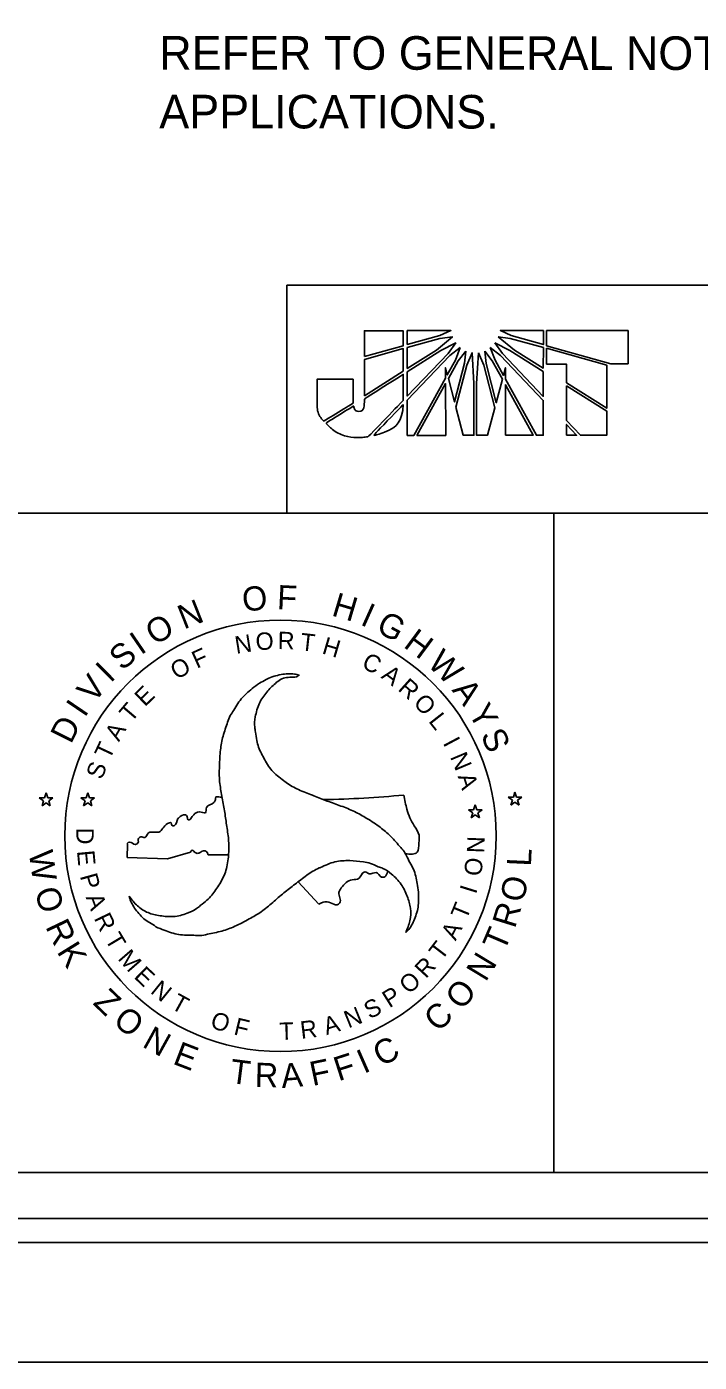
# Model space of a CAD drawing. Extents: x 1403867 to 1405555, y 486423 to 487523.
# Drawn here: x 1405174.3 to 1405314.5, y 486422.7 to 486701.2 of the extents above; entities that cross this region are included whole.
import ezdxf

# ---------------------------------------------------------------- set-up
doc = ezdxf.new("R2010")
doc.units = 0
for name, color, linetype in [('Default', 7, 'Continuous'), ('DEV BORDER CELL', 7, 'Continuous'), ('DEV DOT SWIRL SEAL CELL', 7, 'Continuous'), ('Sheet Plan CELL', 7, 'Continuous'), ('Sheet Plot Border Outside CELL', 7, 'Continuous'), ('Text', 7, 'Continuous')]:
    doc.layers.add(name, color=color, linetype=linetype)

msp = doc.modelspace()

# ---------------------------------------------------------------- linework, layer by layer
at = {"layer": 'Default'}
for p, q in [((1405252.78, 486637.79), (1405244.69, 486637.79)), ((1405244.69, 486637.79), (1405244.69, 486632.42)), ((1405252.79, 486634.67), (1405252.78, 486637.79)), ((1405262.74, 486637.84), (1405253.62, 486637.83)), ((1405253.62, 486637.83), (1405253.63, 486634.94)), ((1405253.63, 486634.94), (1405260.41, 486636.81)), ((1405260.41, 486636.18), (1405253.63, 486634.31)), ((1405259.71, 486633.78), (1405263.06, 486636.51)), ((1405260.41, 486636.81), (1405262.74, 486637.84)), ((1405263.06, 486636.51), (1405260.41, 486636.18)), ((1405272.6, 486636.52), (1405275.99, 486633.74)), ((1405275.1, 486636.2), (1405272.6, 486636.52)), ((1405282.03, 486637.82), (1405273.05, 486637.85)), ((1405273.05, 486637.85), (1405275.32, 486636.79)), ((1405282.03, 486634.29), (1405275.1, 486636.2)), ((1405275.32, 486636.79), (1405282.03, 486634.91)), ((1405282.03, 486634.91), (1405282.03, 486637.82)), ((1405299.68, 486637.88), (1405282.66, 486637.86)), ((1405282.66, 486637.86), (1405282.66, 486634.73)), ((1405299.68, 486630.9), (1405299.68, 486637.88)), ((1405244.69, 486632.42), (1405252.79, 486634.67)), ((1405252.79, 486634.08), (1405244.69, 486631.8)), ((1405252.79, 486629.39), (1405252.79, 486634.08)), ((1405253.63, 486634.31), (1405253.63, 486629.93)), ((1405253.63, 486629.93), (1405259.71, 486633.78)), ((1405260.64, 486633.69), (1405253.63, 486629.22)), ((1405253.64, 486624.17), (1405262.17, 486633.06)), ((1405262.51, 486632.62), (1405253.64, 486623.31)), ((1405263.73, 486635.25), (1405260.64, 486633.69)), ((1405262.17, 486633.06), (1405263.73, 486635.25)), ((1405264.66, 486634.28), (1405262.51, 486632.62)), ((1405263.68, 486631.69), (1405264.66, 486634.28)), ((1405265.83, 486633.56), (1405264.22, 486631.5)), ((1405265.6, 486631.06), (1405265.83, 486633.56)), ((1405267.16, 486633.2), (1405266.06, 486630.61)), ((1405267.52, 486626.81), (1405267.16, 486633.2)), ((1405268.5, 486633.2), (1405268.09, 486626.81)), ((1405269.57, 486630.61), (1405268.5, 486633.2)), ((1405269.79, 486633.56), (1405270.06, 486630.97)), ((1405271.36, 486631.5), (1405269.79, 486633.56)), ((1405270.94, 486634.28), (1405271.93, 486631.69)), ((1405273.09, 486632.63), (1405270.94, 486634.28)), ((1405271.89, 486635.26), (1405273.46, 486633.03)), ((1405275.02, 486633.7), (1405271.89, 486635.26)), ((1405281.99, 486623.26), (1405273.09, 486632.63)), ((1405273.46, 486633.03), (1405281.99, 486624.1)), ((1405281.98, 486629.28), (1405275.02, 486633.7)), ((1405275.99, 486633.74), (1405281.98, 486630)), ((1405281.98, 486630), (1405282.03, 486634.29)), ((1405282.66, 486634.73), (1405282.66, 486634.64)), ((1405282.66, 486634.64), (1405296.06, 486630.9)), ((1405282.66, 486634.16), (1405282.66, 486634.11)), ((1405295.21, 486630.59), (1405282.66, 486634.16)), ((1405282.66, 486634.11), (1405282.66, 486630.85)), ((1405244.69, 486631.8), (1405244.7, 486624.25)), ((1405261.58, 486627.93), (1405261.58, 486630.07)), ((1405261.58, 486630.07), (1405261.98, 486628.6)), ((1405261.98, 486628.6), (1405263.68, 486631.69)), ((1405264.22, 486631.5), (1405262.21, 486627.84)), ((1405263.51, 486622.97), (1405265.6, 486631.06)), ((1405266.06, 486630.61), (1405263.78, 486621.85)), ((1405271.9, 486621.73), (1405269.57, 486630.61)), ((1405270.06, 486630.97), (1405272.17, 486622.79)), ((1405273.46, 486627.71), (1405271.36, 486631.5)), ((1405271.93, 486631.69), (1405273.67, 486628.47)), ((1405273.67, 486628.47), (1405274.09, 486630.08)), ((1405274.09, 486630.08), (1405274.09, 486627.71)), ((1405282.66, 486630.85), (1405286.82, 486630.85)), ((1405286.82, 486630.85), (1405286.82, 486626.96)), ((1405295.22, 486621.65), (1405295.21, 486630.59)), ((1405296.06, 486630.9), (1405299.68, 486630.9)), ((1405244.7, 486624.25), (1405252.79, 486629.39)), ((1405253.63, 486629.22), (1405253.64, 486624.17)), ((1405254.98, 486615.97), (1405261.58, 486627.93)), ((1405262.21, 486627.84), (1405263.51, 486622.97)), ((1405272.17, 486622.79), (1405273.46, 486627.71)), ((1405274.09, 486627.71), (1405280.56, 486615.99)), ((1405281.99, 486624.1), (1405281.98, 486629.28)), ((1405261.58, 486626.77), (1405255.61, 486615.97)), ((1405261.65, 486615.97), (1405261.58, 486626.77)), ((1405267.52, 486616.02), (1405267.52, 486626.81)), ((1405268.09, 486626.81), (1405268.1, 486616.02)), ((1405279.9, 486616.03), (1405274.09, 486626.55)), ((1405274.09, 486626.55), (1405274.1, 486616.02)), ((1405286.82, 486626.96), (1405295.22, 486621.65)), ((1405286.82, 486626.29), (1405286.83, 486619.05)), ((1405295.22, 486621.03), (1405286.82, 486626.29)), ((1405253.64, 486623.31), (1405253.64, 486615.96)), ((1405263.78, 486621.85), (1405265.31, 486616.01)), ((1405270.34, 486616.02), (1405271.9, 486621.73)), ((1405281.99, 486615.99), (1405281.99, 486623.26)), ((1405286.83, 486619.05), (1405289.73, 486616)), ((1405295.22, 486616), (1405295.22, 486621.03)), ((1405253.64, 486615.96), (1405254.98, 486615.97)), ((1405255.61, 486615.97), (1405261.65, 486615.97)), ((1405265.31, 486616.01), (1405267.52, 486616.02)), ((1405268.1, 486616.02), (1405270.34, 486616.02)), ((1405274.1, 486616.02), (1405279.9, 486616.03)), ((1405280.56, 486615.99), (1405281.99, 486615.99)), ((1405288.93, 486616), (1405286.83, 486618.27)), ((1405286.83, 486618.27), (1405286.83, 486615.99)), ((1405286.83, 486615.99), (1405288.93, 486616)), ((1405289.73, 486616), (1405295.22, 486616))]:
    msp.add_line(p, q, dxfattribs=at)
for points in [[(1405244.69, 486632.42), (1405252.79, 486634.67), (1405252.78, 486637.79), (1405244.69, 486637.79), (1405244.69, 486632.42)], [(1405260.41, 486636.81), (1405262.74, 486637.84), (1405253.62, 486637.83), (1405253.63, 486634.94), (1405260.41, 486636.81)], [(1405253.63, 486634.31), (1405253.63, 486629.93), (1405259.71, 486633.78), (1405263.06, 486636.51), (1405260.41, 486636.18), (1405253.63, 486634.31)], [(1405272.6, 486636.52), (1405275.99, 486633.74), (1405281.98, 486630), (1405282.03, 486634.29), (1405275.1, 486636.2), (1405272.6, 486636.52)], [(1405275.32, 486636.79), (1405282.03, 486634.91), (1405282.03, 486637.82), (1405273.05, 486637.85), (1405275.32, 486636.79)], [(1405244.7, 486624.25), (1405252.79, 486629.39), (1405252.79, 486634.08), (1405244.69, 486631.8), (1405244.7, 486624.25)], [(1405253.63, 486629.22), (1405253.64, 486624.17), (1405262.17, 486633.06), (1405263.73, 486635.25), (1405260.64, 486633.69), (1405253.63, 486629.22)], [(1405264.66, 486634.28), (1405262.51, 486632.62), (1405253.64, 486623.31), (1405253.64, 486615.96), (1405254.98, 486615.97), (1405261.58, 486627.93), (1405261.58, 486630.07), (1405261.98, 486628.6), (1405263.68, 486631.69), (1405264.66, 486634.28)], [(1405265.83, 486633.56), (1405264.22, 486631.5), (1405262.21, 486627.84), (1405263.51, 486622.97), (1405265.6, 486631.06), (1405265.83, 486633.56)], [(1405266.06, 486630.61), (1405263.78, 486621.85), (1405265.31, 486616.01), (1405267.52, 486616.02), (1405267.52, 486626.81), (1405267.16, 486633.2), (1405266.06, 486630.61)], [(1405268.5, 486633.2), (1405268.09, 486626.81), (1405268.1, 486616.02), (1405270.34, 486616.02), (1405271.9, 486621.73), (1405269.57, 486630.61), (1405268.5, 486633.2)], [(1405269.79, 486633.56), (1405270.06, 486630.97), (1405272.17, 486622.79), (1405273.46, 486627.71), (1405271.36, 486631.5), (1405269.79, 486633.56)], [(1405270.94, 486634.28), (1405271.93, 486631.69), (1405273.67, 486628.47), (1405274.09, 486630.08), (1405274.09, 486627.71), (1405280.56, 486615.99), (1405281.99, 486615.99), (1405281.99, 486623.26), (1405273.09, 486632.63), (1405270.94, 486634.28)], [(1405271.89, 486635.26), (1405273.46, 486633.03), (1405281.99, 486624.1), (1405281.98, 486629.28), (1405275.02, 486633.7), (1405271.89, 486635.26)], [(1405282.66, 486634.16), (1405282.66, 486634.11), (1405282.66, 486630.85), (1405286.82, 486630.85), (1405286.82, 486626.96), (1405295.22, 486621.65), (1405295.21, 486630.59), (1405282.66, 486634.16)], [(1405255.61, 486615.97), (1405261.65, 486615.97), (1405261.58, 486626.77), (1405255.61, 486615.97)], [(1405274.1, 486616.02), (1405279.9, 486616.03), (1405274.09, 486626.55), (1405274.1, 486616.02)], [(1405286.82, 486626.29), (1405286.83, 486619.05), (1405289.73, 486616), (1405295.22, 486616), (1405295.22, 486621.03), (1405286.82, 486626.29), (1405286.82, 486626.29)], [(1405286.83, 486615.99), (1405286.83, 486615.99), (1405288.93, 486616), (1405286.83, 486618.27), (1405286.83, 486615.99)]]:
    msp.add_lwpolyline(points, dxfattribs=at)
for points in [[(1405242.37, 486627.72), (1405242.37, 486627.72), (1405234.88, 486627.72), (1405234.88, 486627.72), (1405234.88, 486627.72), (1405234.88, 486623.03), (1405234.88, 486623.03), (1405234.88, 486623.03), (1405234.88, 486622.53), (1405234.88, 486622.53), (1405234.88, 486621.06), (1405235.36, 486619.9), (1405236.22, 486618.93), (1405236.22, 486618.93), (1405242.37, 486622.67), (1405242.37, 486622.77), (1405242.37, 486622.77), (1405242.37, 486627.72), (1405242.37, 486627.72)], [(1405242.37, 486627.72), (1405242.37, 486627.72), (1405234.88, 486627.72), (1405234.88, 486627.72), (1405234.88, 486627.72), (1405234.88, 486623.03), (1405234.88, 486623.03), (1405234.88, 486623.03), (1405234.88, 486622.53), (1405234.88, 486622.53), (1405234.88, 486621.06), (1405235.36, 486619.9), (1405236.22, 486618.93), (1405236.22, 486618.93), (1405242.37, 486622.67), (1405242.37, 486622.77), (1405242.37, 486622.77), (1405242.37, 486627.72), (1405242.37, 486627.72)], [(1405243.54, 486620.98), (1405243.06, 486620.98), (1405242.64, 486621.25), (1405242.47, 486622.14), (1405242.47, 486622.14), (1405236.66, 486618.54), (1405236.66, 486618.54), (1405238.45, 486616.66), (1405241.31, 486615.54), (1405243.73, 486615.54), (1405244.36, 486615.54), (1405244.84, 486615.6), (1405245.51, 486615.73), (1405245.51, 486615.73), (1405252.8, 486623.27), (1405252.8, 486623.27), (1405252.8, 486623.27), (1405252.79, 486628.72), (1405252.79, 486628.72), (1405252.79, 486628.72), (1405244.7, 486623.57), (1405244.7, 486623.57), (1405244.7, 486621.53), (1405244.21, 486620.98), (1405243.54, 486620.98)], [(1405243.54, 486620.98), (1405243.06, 486620.98), (1405242.64, 486621.25), (1405242.47, 486622.14), (1405242.47, 486622.14), (1405236.66, 486618.54), (1405236.66, 486618.54), (1405238.45, 486616.66), (1405241.31, 486615.54), (1405243.73, 486615.54), (1405244.36, 486615.54), (1405244.84, 486615.6), (1405245.51, 486615.73), (1405245.51, 486615.73), (1405252.8, 486623.27), (1405252.8, 486623.27), (1405252.8, 486623.27), (1405252.79, 486628.72), (1405252.79, 486628.72), (1405252.79, 486628.72), (1405244.7, 486623.57), (1405244.7, 486623.57), (1405244.7, 486621.53), (1405244.21, 486620.98), (1405243.54, 486620.98)], [(1405252.8, 486622.42), (1405252.8, 486622.42), (1405246.5, 486615.9), (1405246.5, 486615.9), (1405249.58, 486616.67), (1405252.65, 486618.72), (1405252.8, 486622.42)], [(1405252.8, 486622.42), (1405252.8, 486622.42), (1405246.5, 486615.9), (1405246.5, 486615.9), (1405249.58, 486616.67), (1405252.65, 486618.72), (1405252.8, 486622.42)]]:
    msp.add_open_spline(points, degree=3, dxfattribs=at)
at = {"layer": 'DEV BORDER CELL'}
for p, q in [((1404608.13, 486452.72), (1405520.08, 486452.72)), ((1404040.64, 486447.72), (1405520.08, 486447.72))]:
    msp.add_line(p, q, dxfattribs=at)
for points in [[(1405170.21, 486599.77), (1405284.21, 486599.77), (1405284.21, 486462.27), (1405170.21, 486462.27)], [(1405520.21, 486599.77), (1405284.21, 486599.77), (1405284.21, 486462.27), (1405520.21, 486462.27)]]:
    msp.add_lwpolyline(points, close=True, dxfattribs=at)
at = {"layer": 'DEV DOT SWIRL SEAL CELL'}
for p, q in [((1405178.35, 486541.44), (1405178.03, 486540.44)), ((1405178.71, 486540.44), (1405178.35, 486541.44)), ((1405187.02, 486541.42), (1405186.7, 486540.42)), ((1405187.39, 486540.42), (1405187.02, 486541.42)), ((1405276.07, 486541.58), (1405275.75, 486540.58)), ((1405276.43, 486540.58), (1405276.07, 486541.58)), ((1405176.94, 486540.44), (1405177.82, 486539.79)), ((1405178.03, 486540.44), (1405176.94, 486540.44)), ((1405177.82, 486539.79), (1405177.5, 486538.75)), ((1405177.5, 486538.75), (1405178.35, 486539.39)), ((1405178.35, 486539.39), (1405179.23, 486538.75)), ((1405178.35, 486539.39), (1405179.23, 486538.75)), ((1405179.79, 486540.44), (1405178.71, 486540.44)), ((1405178.91, 486539.79), (1405179.79, 486540.44)), ((1405178.91, 486539.79), (1405179.79, 486540.44)), ((1405179.23, 486538.75), (1405178.91, 486539.79)), ((1405179.23, 486538.75), (1405178.91, 486539.79)), ((1405186.7, 486540.42), (1405185.62, 486540.42)), ((1405185.62, 486540.42), (1405186.5, 486539.78)), ((1405186.5, 486539.78), (1405186.18, 486538.74)), ((1405186.18, 486538.74), (1405187.02, 486539.38)), ((1405187.02, 486539.38), (1405187.91, 486538.74)), ((1405188.47, 486540.42), (1405187.39, 486540.42)), ((1405187.59, 486539.78), (1405188.47, 486540.42)), ((1405187.91, 486538.74), (1405187.59, 486539.78)), ((1405267.47, 486537.93), (1405266.39, 486537.93)), ((1405266.39, 486537.93), (1405267.27, 486537.29)), ((1405267.79, 486538.93), (1405267.47, 486537.93)), ((1405268.15, 486537.93), (1405267.79, 486538.93)), ((1405269.24, 486537.93), (1405268.15, 486537.93)), ((1405268.35, 486537.29), (1405269.24, 486537.93)), ((1405275.75, 486540.58), (1405274.66, 486540.58)), ((1405274.66, 486540.58), (1405275.55, 486539.93)), ((1405275.55, 486539.93), (1405275.23, 486538.89)), ((1405275.23, 486538.89), (1405276.07, 486539.53)), ((1405276.07, 486539.53), (1405276.96, 486538.89)), ((1405277.52, 486540.58), (1405276.43, 486540.58)), ((1405276.63, 486539.93), (1405277.52, 486540.58)), ((1405276.96, 486538.89), (1405276.63, 486539.93)), ((1405267.27, 486537.29), (1405266.95, 486536.25)), ((1405266.95, 486536.25), (1405267.79, 486536.89)), ((1405267.79, 486536.89), (1405268.68, 486536.25)), ((1405268.68, 486536.25), (1405268.35, 486537.29)), ((1405195.27, 486527.99), (1405195.35, 486530.65)), ((1405203.66, 486527.68), (1405195.27, 486527.99)), ((1405208.46, 486529.09), (1405203.66, 486527.68)), ((1405212.16, 486528.53), (1405216.38, 486528.49)), ((1405230.91, 486522.91), (1405235.22, 486518.24))]:
    msp.add_line(p, q, dxfattribs=at)
for start, end in [(271.2035, 275.3236), (265.6785, 265.9762)]:
    msp.add_arc((1405231.3, 486773.17), 233.19, start, end, dxfattribs=at)
for points in [[(1405195.68, 486519.88), (1405197.42, 486517.87), (1405199.6, 486516.47), (1405202.1, 486515.83), (1405204.91, 486515.66), (1405207.79, 486516.34), (1405209.69, 486517.3), (1405210.5, 486517.94), (1405211.89, 486519.05), (1405212.89, 486520.12), (1405214.55, 486522.48), (1405215.84, 486525.27), (1405216.38, 486528.47), (1405216.4, 486528.74), (1405216.38, 486531.74), (1405215.97, 486534.78), (1405215.54, 486537.7), (1405215.01, 486540.74), (1405214.53, 486543.74), (1405214.47, 486546.67), (1405214.66, 486550.03), (1405215.14, 486552.9), (1405216.08, 486555.85), (1405216.59, 486557.25), (1405217.29, 486558.38), (1405219.03, 486561.03), (1405221.32, 486563.18), (1405222.82, 486564.31), (1405224.24, 486565.06), (1405224.48, 486565.19), (1405227.33, 486566.1), (1405230.12, 486566.21), (1405231.06, 486565.97)], [(1405231.14, 486566.05), (1405231.06, 486565.97), (1405228.48, 486565.49), (1405226.15, 486564.28), (1405224.35, 486562.45), (1405222.82, 486560.12), (1405221.96, 486557.27), (1405221.83, 486555.15), (1405222.01, 486554.13), (1405222.26, 486552.36), (1405222.66, 486550.96), (1405223.92, 486548.36), (1405225.66, 486545.84), (1405228.19, 486543.77), (1405228.4, 486543.61), (1405230.98, 486542.13), (1405233.85, 486540.95), (1405236.59, 486539.88), (1405239.46, 486538.83), (1405242.31, 486537.7), (1405244.88, 486536.31), (1405247.71, 486534.48), (1405249.93, 486532.63), (1405252.03, 486530.35), (1405252.99, 486529.19), (1405253.61, 486528.01), (1405255.06, 486525.19), (1405255.76, 486522.13), (1405256, 486520.26), (1405255.95, 486518.64), (1405255.95, 486518.38), (1405255.27, 486515.45), (1405253.96, 486512.98), (1405253.31, 486512.31)], [(1405253.24, 486528.76), (1405255.71, 486529.06), (1405256.08, 486531.01), (1405256.1, 486532.65), (1405255.09, 486534.55), (1405253.56, 486538.02), (1405252.94, 486540.99)], [(1405195.35, 486530.65), (1405195.27, 486530.9), (1405195.72, 486531.18), (1405196.96, 486530.67), (1405197.58, 486531.21), (1405197.56, 486531.75), (1405198.07, 486532.29), (1405198.91, 486532.11), (1405199.68, 486533.08), (1405200.38, 486533.28), (1405201.88, 486533.28), (1405203.66, 486535.05), (1405204.39, 486535.17), (1405204.59, 486534.69), (1405205.04, 486534.6), (1405205.83, 486536.07), (1405206.03, 486536.27), (1405207.39, 486536.83), (1405207.76, 486536.55), (1405207.87, 486535.9), (1405208.07, 486535.79), (1405208.52, 486536.1), (1405209.14, 486536.89), (1405210.27, 486537.49), (1405211.57, 486537.31), (1405211.8, 486538.39), (1405213.32, 486539.41), (1405213.63, 486540.03), (1405213.72, 486540.65)], [(1405253.31, 486512.31), (1405254.17, 486514.78), (1405254.31, 486517.38), (1405253.61, 486519.88), (1405252.35, 486522.37), (1405250.33, 486524.52), (1405248.56, 486525.7), (1405247.57, 486526.05), (1405245.96, 486526.75), (1405244.48, 486527.07), (1405241.64, 486527.31), (1405238.55, 486527.05), (1405235.52, 486525.89), (1405235.27, 486525.78), (1405232.7, 486524.26), (1405230.25, 486522.4), (1405227.92, 486520.58), (1405225.59, 486518.59), (1405223.19, 486516.66), (1405220.7, 486515.15), (1405217.69, 486513.62), (1405214.98, 486512.63), (1405211.98, 486511.96), (1405210.47, 486511.69), (1405209.15, 486511.75), (1405206.01, 486511.91), (1405202.98, 486512.82), (1405201.26, 486513.54), (1405199.89, 486514.43), (1405199.65, 486514.56), (1405197.45, 486516.58), (1405195.98, 486518.94), (1405195.68, 486519.88)], [(1405212.16, 486528.53), (1405211.82, 486529.18), (1405211.15, 486529.37), (1405210.21, 486528.9), (1405209.54, 486528.92), (1405208.77, 486529.49), (1405208.46, 486529.09)], [(1405235.22, 486518.24), (1405236.92, 486518.75), (1405238.33, 486518.21), (1405239.01, 486518.1), (1405239.58, 486518.52), (1405239.4, 486520.64), (1405239.89, 486521.63), (1405242.17, 486523.33), (1405243.59, 486523.64), (1405244.63, 486524.94), (1405245.06, 486524.91), (1405245.7, 486524.54), (1405247.15, 486524.83), (1405248.3, 486523.89), (1405248.98, 486523.95), (1405249.53, 486525.01)]]:
    msp.add_spline(points, degree=3, dxfattribs=at)
at = {"layer": 'Sheet Plan CELL'}
msp.add_lwpolyline([(1405520.21, 486647.29), (1405228.54, 486647.29), (1405228.54, 486599.77), (1405520.21, 486599.77)], close=True, dxfattribs=at)
at = {"layer": 'Sheet Plot Border Outside CELL'}
for points in [[(1403867.36, 486422.72), (1403867.36, 487522.72), (1405555.36, 487522.72), (1405555.36, 486422.72)], [(1403867.36, 487522.72), (1405555.36, 487522.72), (1405555.36, 486422.72), (1403867.36, 486422.72)], [(1403867.36, 486422.72), (1405555.36, 486422.72), (1405555.36, 487522.72), (1403867.36, 487522.72)]]:
    msp.add_lwpolyline(points, close=True, dxfattribs=at)
at = {"layer": 'Text'}
msp.add_circle((1405227.21, 486532.48), 44.97, dxfattribs=at)

# ---------------------------------------------------------------- texts
at = {"layer": 'DEV BORDER CELL'}
for s, p in [('REFER TO GENERAL NOTES FOR NUMBER OF', (1405201.94, 486692.25)), ('APPLICATIONS.', (1405201.94, 486680))]:
    msp.add_text(s, height=7, rotation=359.9598, dxfattribs=at).set_placement(p)
at = {"layer": 'DEV DOT SWIRL SEAL CELL'}
for s, height, rotation, p in [('O', 5.04, 5.7649, (1405219.47, 486579.21)), ('F', 5.04, 357.2575, (1405226.42, 486579.76)), ('H', 5.04, 343.454, (1405237.66, 486578.47)), ('N', 5.04, 21.5861, (1405207.07, 486575.48)), ('I', 5.04, 335.804, (1405243.65, 486576.6)), ('O', 5.04, 30.0935, (1405200.96, 486572.1)), ('G', 5.04, 331.5167, (1405246.88, 486575.21)), ('I', 5.04, 34.3808, (1405198.09, 486570.07)), ('N', 3.63, 9.0227, (1405217.99, 486570.42)), ('O', 3.63, 3.9446, (1405222.14, 486571.14)), ('R', 3.63, 358.8665, (1405226.61, 486571.42)), ('H', 5.04, 323.4632, (1405252.64, 486571.96)), ('S', 5.04, 40.5848, (1405194.22, 486566.76)), ('F', 3.63, 24.2569, (1405209.77, 486567.3)), ('H', 3.63, 343.6322, (1405235.69, 486570.55)), ('W', 5.04, 315.8133, (1405257.63, 486568.16)), ('I', 5.04, 44.8722, (1405191.76, 486564.23)), ('O', 3.63, 29.335, (1405205.56, 486564.95)), ('C', 3.63, 333.4761, (1405243.92, 486567.63)), ('V', 5.04, 51.5806, (1405188.32, 486559.94)), ('A', 3.63, 323.3199, (1405248.02, 486565.51)), ('E', 3.63, 44.5692, (1405198.95, 486559.27)), ('R', 3.63, 318.2418, (1405251.51, 486562.95)), ('A', 5.04, 306.7762, (1405262.81, 486562.86)), ('I', 5.04, 55.8679, (1405186.39, 486556.99)), ('T', 3.63, 49.6473, (1405196.09, 486555.96)), ('O', 3.63, 313.1637, (1405254.72, 486560.04)), ('Y', 5.04, 299.7484, (1405266.23, 486558.22)), ('L', 3.63, 308.0856, (1405257.94, 486556.37)), ('D', 5.04, 63.459, (1405183.54, 486551.46)), ('A', 3.63, 59.8035, (1405193.53, 486551.97)), ('S', 5.04, 293.2249, (1405268.87, 486553.56)), ('T', 3.63, 64.8816, (1405191.59, 486548.18)), ('I', 3.63, 297.9295, (1405260.99, 486551.86)), ('N', 3.63, 292.8514, (1405262.5, 486548.96)), ('S', 3.63, 69.9597, (1405190, 486544.04)), ('A', 3.63, 287.7733, (1405264.1, 486544.9)), ('D', 3.63, 270.272, (1405184.66, 486534.18)), ('N', 3.63, 87.733, (1405269.66, 486528.82)), ('E', 3.63, 275.3501, (1405184.78, 486529.32)), ('O', 3.63, 82.9269, (1405269.03, 486523.95)), ('P', 3.63, 285.5063, (1405185.38, 486524.11)), ('I', 3.63, 72.7707, (1405267.95, 486520.19)), ('A', 3.63, 290.5843, (1405186.58, 486519.66)), ('T', 3.63, 67.6926, (1405265.95, 486514.8)), ('R', 3.63, 295.6624, (1405188.25, 486515.32)), ('A', 3.63, 62.6145, (1405263.72, 486510.46)), ('T', 3.63, 300.7405, (1405190.53, 486510.92)), ('T', 3.63, 52.4584, (1405260.77, 486506.32)), ('M', 3.63, 310.8967, (1405193.15, 486506.82)), ('E', 3.63, 315.9748, (1405196.49, 486503)), ('R', 3.63, 47.3803, (1405257.51, 486502.58)), ('N', 3.63, 321.0529, (1405199.91, 486499.84)), ('O', 3.63, 42.3022, (1405253.99, 486499.31)), ('T', 3.63, 331.209, (1405204.15, 486496.6)), ('P', 3.63, 32.146, (1405249.91, 486496.49)), ('N', 3.63, 21.9899, (1405241.37, 486492.31)), ('S', 3.63, 27.068, (1405245.78, 486494.19)), ('O', 3.63, 341.3652, (1405212.36, 486492.58)), ('F', 3.63, 346.4433, (1405217.29, 486491.11)), ('T', 3.63, 1.6775, (1405227.05, 486489.91)), ('R', 3.63, 6.7556, (1405231.54, 486490.15)), ('A', 3.63, 16.9118, (1405236.79, 486490.92))]:
    msp.add_text(s, height=height, rotation=rotation, dxfattribs=at).set_placement(p)
at = {"layer": 'Text'}
for s, height, rotation, p in [('T', 3.63, 353.7884, (1405231.24, 486571.19)), ('W', 5.04, 278.15, (1405174.73, 486529.1)), ('L', 5.04, 87.429, (1405279.41, 486526.03)), ('O', 5.04, 287.1147, (1405175.89, 486520.97)), ('O', 5.04, 78.9896, (1405277.9, 486518.44)), ('R', 5.04, 72.7519, (1405276.07, 486513.01)), ('R', 5.04, 295.5541, (1405178.14, 486513.56)), ('T', 5.04, 66.881, (1405273.83, 486508.12)), ('K', 5.04, 301.7918, (1405180.48, 486508.34)), ('N', 5.04, 58.892, (1405269.99, 486501.88)), ('O', 5.04, 50.4526, (1405265.03, 486495.93)), ('Z', 5.04, 316.1688, (1405187.94, 486497.49)), ('O', 5.04, 322.5233, (1405192.05, 486493.36)), ('C', 5.04, 43.0807, (1405260.03, 486491.38)), ('N', 5.04, 330.9626, (1405198.18, 486488.63)), ('E', 5.04, 338.9517, (1405204.55, 486485.02)), ('I', 5.04, 23.7503, (1405244.58, 486482.83)), ('C', 5.04, 28.0033, (1405248.21, 486484.26)), ('T', 5.04, 352.6948, (1405216.48, 486480.99)), ('R', 5.04, 358.5656, (1405221.8, 486480.16)), ('A', 5.04, 4.8034, (1405227.52, 486479.88)), ('F', 5.04, 11.7751, (1405233.9, 486480.31)), ('F', 5.04, 17.7627, (1405239.3, 486481.29))]:
    msp.add_text(s, height=height, rotation=rotation, dxfattribs=at).set_placement(p)

doc.saveas('drawing.dxf')
